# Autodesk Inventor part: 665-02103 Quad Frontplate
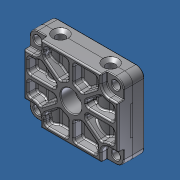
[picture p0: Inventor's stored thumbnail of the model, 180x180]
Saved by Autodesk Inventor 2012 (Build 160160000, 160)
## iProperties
Created: 2013-10
Part Number: 665-02103 Quad Frontplate
Material: Default
Document SubType Name: Modeling
Designer: Admin
Density: 1 g/cm^3
Author: Admin
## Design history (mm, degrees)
node "665-02103 Quad Frontplate1"
node "Base1"
body "Solid1"
